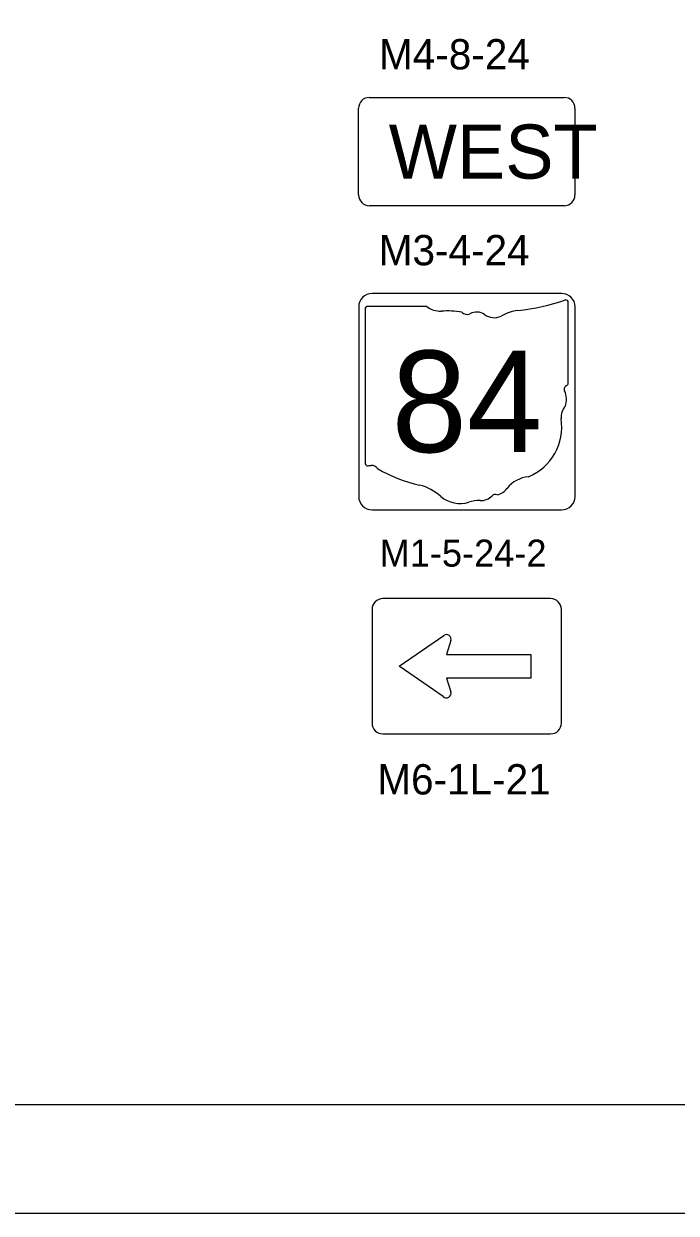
# Model space of a CAD drawing. Extents: x 0 to 54.8, y 0 to 22.
# Drawn here: x 27.97 to 30.99, y 0 to 5.5 of the extents above; entities that cross this region are included whole.
import ezdxf

# ---------------------------------------------------------------- set-up
doc = ezdxf.new("R2010")
doc.units = 0
for name, color, linetype in [('GM_X_County', 7, 'Continuous'), ('GM_X_County_Road', 7, 'Continuous'), ('GM_X_Minor_River_Text', 7, 'Continuous'), ('GM_X_Township', 7, 'Continuous')]:
    doc.layers.add(name, color=color, linetype=linetype)

msp = doc.modelspace()

# ---------------------------------------------------------------- linework, layer by layer
at = {"layer": 'GM_X_County'}
msp.add_lwpolyline([(0, 0), (34, 0), (34, 22), (0, 22)], close=True, dxfattribs=at)
at = {"layer": 'GM_X_Minor_River_Text'}
for p, q in [((29.5675, 5.155), (30.4675, 5.155)), ((29.5175, 4.705), (29.5175, 5.105)), ((30.5175, 5.105), (30.5175, 4.705)), ((30.4675, 4.655), (29.5675, 4.655)), ((29.5486, 4.1776), (29.5486, 3.4661)), ((29.8324, 4.1899), (29.5578, 4.1899)), ((30.4861, 3.8353), (30.4861, 4.2075)), ((30.486, 3.8354), (30.4861, 3.8353)), ((30.405, 2.8397), (29.63, 2.8397)), ((30.4051, 2.8397), (30.405, 2.8397)), ((29.58, 2.7897), (29.58, 2.2647)), ((30.455, 2.2647), (30.455, 2.7897)), ((29.705, 2.5272), (29.9119, 2.6694)), ((29.9437, 2.646), (29.9238, 2.5819)), ((29.9238, 2.5819), (30.3143, 2.5819)), ((30.3143, 2.5819), (30.3143, 2.4724)), ((29.909, 2.3874), (29.705, 2.5272)), ((30.3143, 2.4724), (29.9238, 2.4724)), ((29.9238, 2.4724), (29.9437, 2.4084)), ((29.63, 2.2147), (30.405, 2.2147))]:
    msp.add_line(p, q, dxfattribs=at)
for points in [[(30.4556, 4.2497), (29.5806, 4.2497)], [(29.5181, 4.1872), (29.5181, 3.3122)], [(30.5181, 3.3122), (30.5181, 4.1872)], [(29.5806, 3.2497), (30.4556, 3.2497)]]:
    msp.add_lwpolyline(points, dxfattribs=at)
for centre, radius, start, end in [((29.5675, 5.105), 0.05, 90, 180), ((30.4675, 5.105), 0.05, 0, 90), ((29.5675, 4.705), 0.05, 180, 270), ((30.4675, 4.705), 0.05, 270, 0), ((29.5806, 4.1872), 0.0625, 90, 180), ((30.4556, 4.1872), 0.0625, 0, 90), ((29.5593, 4.1791), 0.0109, 98.1301, 188.1301), ((29.8978, 4.2725), 0.1053, 231.6195, 271.1119), ((30.1521, 5.1599), 0.9942, 275.8445, 288.9065), ((30.4757, 4.2091), 0.0104, 351.8621, 97.738), ((29.9327, 3.7904), 0.3782, 80.4867, 94.9883), ((30.0186, 4.1828), 0.0304, 219.7921, 297.1024), ((30.0632, 4.1006), 0.0632, 54.4667, 119.1411), ((30.1447, 4.2134), 0.076, 233.8562, 294.8282), ((30.279, 3.9725), 0.2, 97.3462, 120.7689), ((30.4837, 3.808), 0.0162, 107.944, 210.337), ((30.3809, 3.7609), 0.097, 340.033, 23.6496), ((30.475, 3.8339), 0.0112, 289.6038, 7.7341), ((30.5235, 3.6795), 0.0705, 136.8065, 186.9296), ((30.2078, 3.6322), 0.2487, 292.3089, 8.9858), ((29.5594, 3.4645), 0.011, 171.9584, 258.3066), ((29.5611, 3.5373), 0.0836, 267.339, 280.6039), ((29.5782, 3.425), 0.0302, 29.7484, 93.2717), ((29.9589, 4.0643), 0.7179, 240.4129, 257.1985), ((29.7448, 3.1464), 0.2246, 47.1842, 75.836), ((30.3127, 3.2663), 0.1362, 94.4031, 142.5768), ((29.5806, 3.3122), 0.0625, 180, 270), ((29.9878, 3.4215), 0.1425, 230.7004, 286.2918), ((30.0806, 3.3682), 0.0759, 268.777, 315.5493), ((30.1493, 3.2993), 0.0214, 65.7517, 132.6484), ((30.1401, 3.3971), 0.0803, 282.8732, 323.2771), ((30.4556, 3.3122), 0.0625, 270, 0), ((30.0701, 3.1755), 0.1171, 85.6951, 111.2099), ((29.6301, 2.7897), 0.05, 90, 180), ((30.4051, 2.7897), 0.05, 0, 90), ((29.9238, 2.6522), 0.0209, 342.7954, 124.5888), ((29.9238, 2.4022), 0.0209, 224.9904, 17.2046), ((29.6301, 2.2647), 0.05, 180, 270), ((30.4051, 2.2647), 0.05, 270, 0)]:
    msp.add_arc(centre, radius, start, end, dxfattribs=at)
at = {"layer": 'GM_X_Township'}
msp.add_lwpolyline([(1.5, 21.5), (33.5, 21.5), (33.5, 0.5), (1.5, 0.5)], close=True, dxfattribs=at)

# ---------------------------------------------------------------- texts
at = {"layer": 'GM_X_County_Road'}
for s, height, p in [('M4-8-24', 0.14, (29.612, 5.2846)), ('M3-4-24', 0.14, (29.6108, 4.3797)), ('M1-5-24-2', 0.125, (29.6149, 2.9872)), ('M6-1L-21', 0.14, (29.6041, 1.9347))]:
    msp.add_text(s, height=height, dxfattribs=at).set_placement(p)
at = {"layer": 'GM_X_Minor_River_Text'}
for s, height, p in [('WEST', 0.25, (29.6568, 4.78)), ('84', 0.46875, (29.6699, 3.5163))]:
    msp.add_text(s, height=height, dxfattribs=at).set_placement(p)

doc.saveas('drawing.dxf')
